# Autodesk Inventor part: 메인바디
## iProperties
Created: 2011-12
Part Number: 메인바디
Document SubType Name: Modeling
Designer: pww
Density: 1 g/cm^3
Material: 기본값
Mass: 231.691 g
Surface Area: 426.167 cm^2
Volume: 231.691 cm^3
Author: pww
